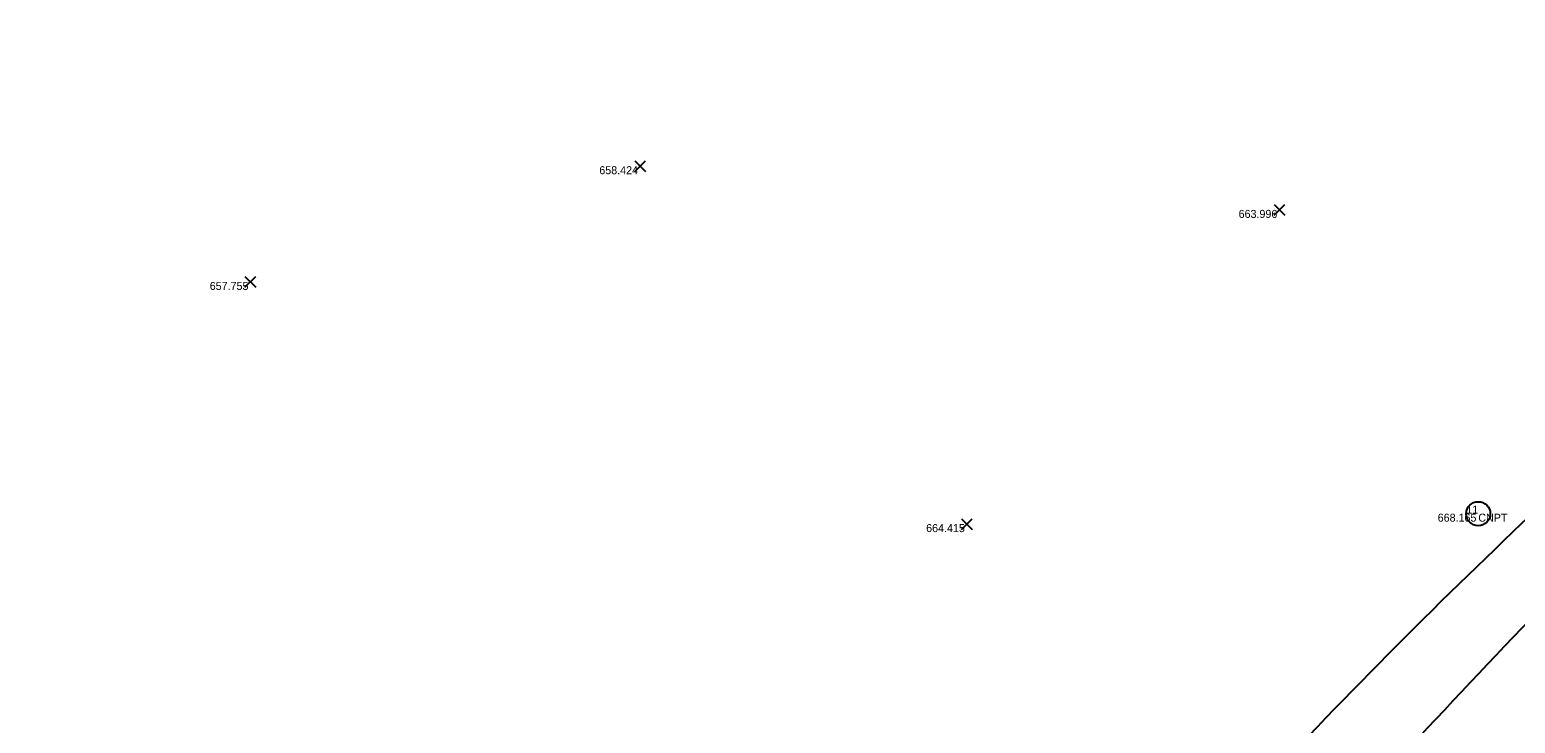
# Model space of a CAD drawing. Extents: x 2197382 to 2204062, y 634117 to 636522.
# Drawn here: x 2202277.4 to 2202463, y 635059.1 to 635145.7 of the extents above; entities that cross this region are included whole.
import ezdxf

# ---------------------------------------------------------------- set-up
doc = ezdxf.new("R2010")
doc.units = 0
for name, color, linetype in [('GE_P_Alignment_100_Distances', 7, 'Continuous'), ('GE_X_Alignment', 7, 'Continuous'), ('RW_X_CL', 7, 'Continuous'), ('RW_X_CL_100_Curve_Data', 7, 'Continuous'), ('SH_Border', 7, 'Continuous'), ('SH_Cut_Line', 7, 'Continuous'), ('SH_Data', 7, 'Continuous')]:
    doc.layers.add(name, color=color, linetype=linetype)

msp = doc.modelspace()

# ---------------------------------------------------------------- linework, layer by layer
at = {"layer": 'GE_P_Alignment_100_Distances'}
for points in [[(2202381.16, 635210.32), (2202366.1, 635204.72), (2202334.8, 635194.56), (2202286.96, 635182.66), (2202239.06, 635169.83), (2202190.57, 635161.31), (2202142.09, 635153.59), (2202092.91, 635148.21), (2202043.66, 635145.11), (2201994.31, 635143.9), (2201945.2, 635145.32), (2201896.27, 635148.27), (2201847.56, 635154.73), (2201798.82, 635161.43), (2201750.63, 635171.43), (2201702.91, 635182.55), (2201655.93, 635196.35), (2201609.49, 635212.58), (2201563.54, 635230.53), (2201517.8, 635250.11), (2201472.75, 635271.46), (2201426.49, 635290.37), (2201396.61, 635304.57), (2201381.57, 635311.27)], [(2202386.45, 635195.59), (2202370.91, 635189.75), (2202339.13, 635180.04), (2202291.09, 635166.72), (2202242.56, 635154.7), (2202193.6, 635144.9), (2202144.21, 635137.83), (2202094.71, 635131.91), (2202044.78, 635129.37), (2201994.9, 635127.35), (2201945.05, 635129.12), (2201895.29, 635131.98), (2201845.71, 635138.04), (2201796.31, 635145.15), (2201747.25, 635154.67), (2201698.84, 635166.79), (2201650.88, 635180.71), (2201603.87, 635197.49), (2201557.29, 635215.61), (2201511.45, 635235.48), (2201465.51, 635255.02), (2201420.2, 635275.98), (2201389.78, 635289.5), (2201374.58, 635296.3)], [(2202514.19, 635120), (2202501.95, 635108.79), (2202477.63, 635085.87), (2202443.41, 635049.36), (2202409.55, 635012.34), (2202376.26, 634974.99), (2202344.34, 634936.42), (2202312.72, 634897.79), (2202282.43, 634858.12), (2202252.58, 634818.18), (2202223.74, 634777.45), (2202196.69, 634735.5), (2202169.8, 634693.41), (2202144.64, 634650.36), (2202119.18, 634607.44), (2202097.03, 634562.79), (2202074.71, 634518.18), (2202053.15, 634473.28), (2202032.85, 634427.72), (2202013.67, 634381.72), (2201995.41, 634335.21), (2201979.19, 634288.02), (2201963.55, 634240.68), (2201953.92, 634208.98), (2201949.13, 634193.1)], [(2202525.02, 635108.11), (2202513.04, 635097.11), (2202489.33, 635074.07), (2202455.07, 635038.62), (2202421.29, 635002.1), (2202388.81, 634964.35), (2202356.35, 634926.75), (2202325.87, 634887.43), (2202295, 634848.95), (2202265.53, 634808.92), (2202237.35, 634768.89), (2202211.52, 634726.54), (2202183.6, 634685.47), (2202158.14, 634642.34), (2202133.69, 634599.43), (2202111.05, 634555.42), (2202088.76, 634511.33), (2202068.04, 634466.33), (2202047.21, 634421.56), (2202027.88, 634376.06), (2202010.16, 634329.7), (2201994.09, 634282.81), (2201978.74, 634235.43), (2201968.75, 634203.87), (2201963.85, 634187.95)]]:
    msp.add_open_spline(points, degree=3, dxfattribs=at)
at = {"layer": 'GE_X_Alignment'}
for points in [[(2202389.25, 635188.21), (2202373.6, 635181.86), (2202342.05, 635172.03), (2202293.67, 635158.58), (2202244.91, 635146.21), (2202194.94, 635137.22), (2202145.31, 635129.1), (2202095.52, 635123.76), (2202045.13, 635120.93), (2201994.93, 635119.27), (2201944.5, 635120.71), (2201894.53, 635123.86), (2201844.41, 635129.5), (2201794.77, 635136.96), (2201745.53, 635147.41), (2201696.65, 635158.71), (2201648.35, 635173.37), (2201600.81, 635189.62), (2201553.51, 635207.06), (2201508.05, 635227.84), (2201462.09, 635247.86), (2201416.63, 635268.36), (2201386.21, 635281.9), (2201371.14, 635288.76)], [(2202540.06, 635152.93), (2202529.43, 635144.25), (2202507.23, 635123.46), (2202471.72, 635092.05), (2202435.62, 635056.76), (2202402.1, 635018.87), (2202368.73, 634981.48), (2202336.15, 634943.25), (2202304.62, 634904.21), (2202274.11, 634864.33), (2202244.37, 634823.83), (2202215.65, 634782.83), (2202187.65, 634741.05), (2202161.54, 634698.56), (2202134.84, 634656), (2202111.41, 634611.66), (2202087.71, 634567.52), (2202064.97, 634523.35), (2202044.2, 634477.97), (2202023.42, 634432.25), (2202003.66, 634386.18), (2201990.91, 634355.55), (2201984.79, 634340.33)], [(2202570.92, 635145.14), (2202556.1, 635132.41), (2202530.6, 635107.02), (2202492.19, 635071.28), (2202457.98, 635035.82), (2202424.73, 634999.38), (2202391.64, 634962.22), (2202359.56, 634924.46), (2202328.32, 634885.6), (2202298.37, 634846.53), (2202268.85, 634806.21), (2202240.94, 634765.59), (2202212.91, 634724.71), (2202187.2, 634682.69), (2202161.14, 634640.35), (2202137.99, 634596.95), (2202114.64, 634553.56), (2202092.28, 634509.95), (2202071.73, 634464.7), (2202050.81, 634420.11), (2202031.84, 634374.34), (2202014.23, 634328.21), (2201997.98, 634281.03), (2201983.22, 634233.69), (2201972.74, 634202.38), (2201968.03, 634186.79)]]:
    msp.add_open_spline(points, degree=3, dxfattribs=at)
at = {"layer": 'RW_X_CL'}
msp.add_circle((2202458.37, 635085.26), 1.5, dxfattribs=at)
msp.add_circle((2202458.37, 635085.26), 1.5, dxfattribs=at)
at = {"layer": 'RW_X_CL_100_Curve_Data'}
for p, q in [((2202353.01, 635128.01), (2202354.35, 635129.34)), ((2202353.01, 635129.34), (2202354.35, 635128.01)), ((2202432.87, 635122.54), (2202434.2, 635123.88)), ((2202432.87, 635123.88), (2202434.2, 635122.54)), ((2202304.29, 635113.54), (2202305.63, 635114.88)), ((2202304.29, 635114.88), (2202305.63, 635113.54)), ((2202393.79, 635083.29), (2202395.13, 635084.63)), ((2202393.79, 635084.63), (2202395.13, 635083.29))]:
    msp.add_line(p, q, dxfattribs=at)

# ---------------------------------------------------------------- texts
at = {"layer": 'SH_Border'}
msp.add_text('CNPT', height=1, dxfattribs=at).set_placement((2202458.37, 635084.26))
msp.add_text('CNPT', height=1, dxfattribs=at).set_placement((2202458.37, 635084.26))
at = {"layer": 'SH_Cut_Line'}
msp.add_text('11', height=1, dxfattribs=at).set_placement((2202456.87, 635085.26))
msp.add_text('11', height=1, dxfattribs=at).set_placement((2202456.87, 635085.26))
at = {"layer": 'SH_Data'}
for s, p in [('658.424', (2202348.56, 635127.67)), ('663.996', (2202428.43, 635122.21)), ('657.755', (2202299.89, 635113.21)), ('668.165', (2202453.3, 635084.26)), ('668.165', (2202453.3, 635084.26)), ('664.415', (2202389.39, 635082.96))]:
    msp.add_text(s, height=1, dxfattribs=at).set_placement(p)

doc.saveas('drawing.dxf')
